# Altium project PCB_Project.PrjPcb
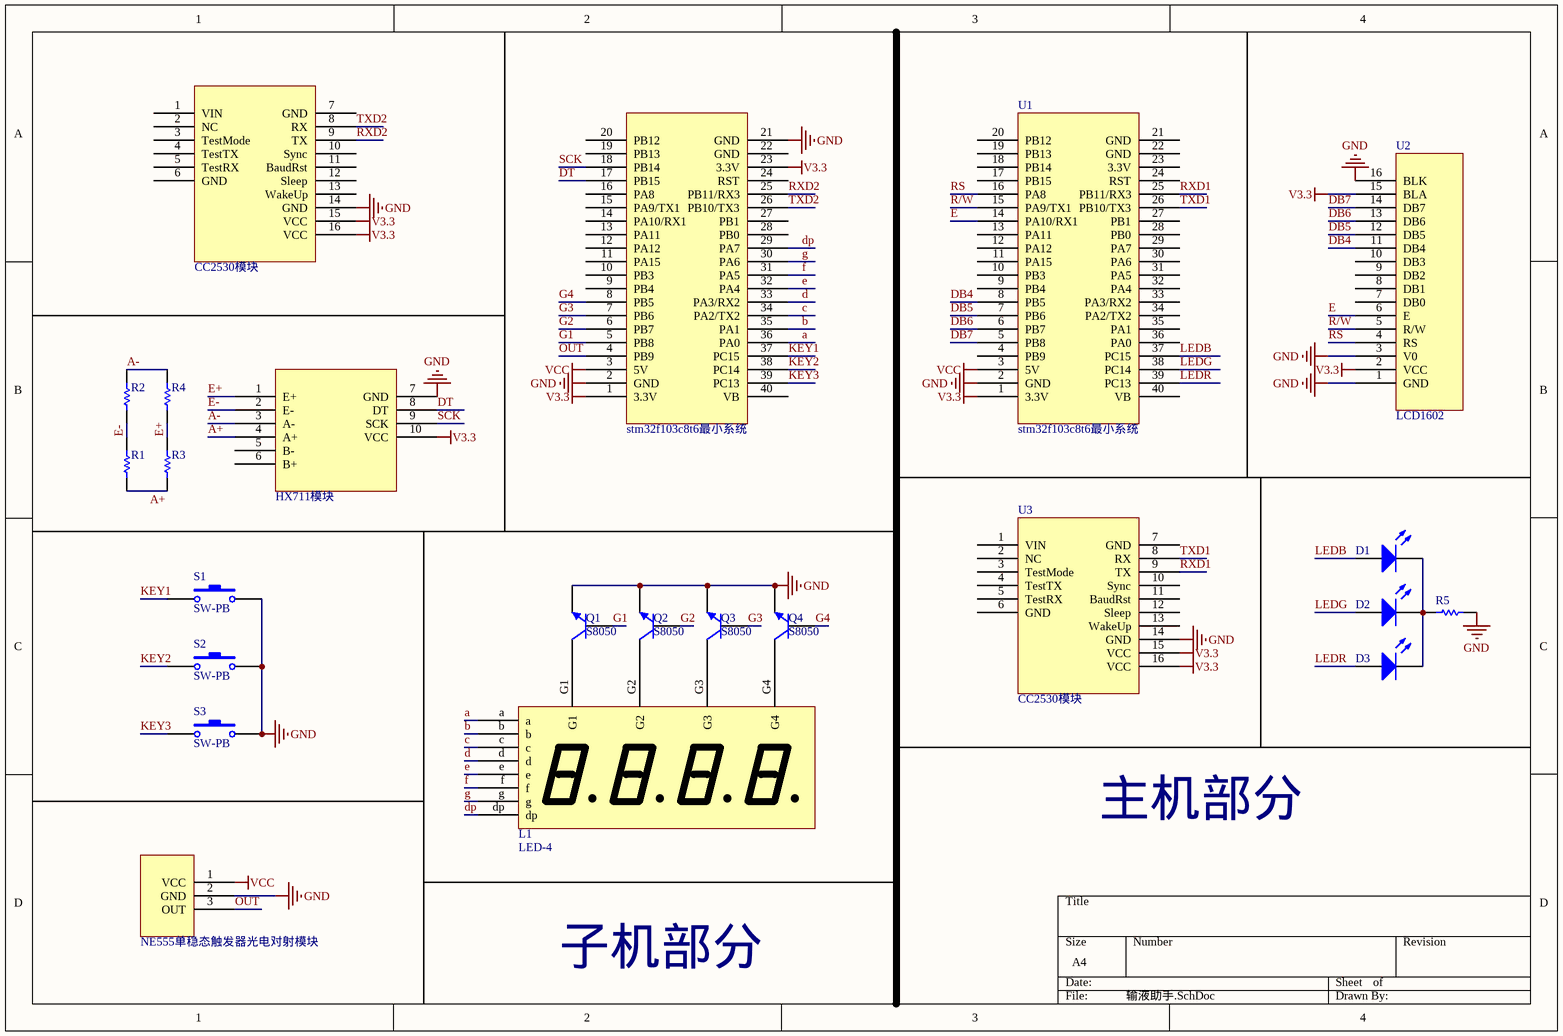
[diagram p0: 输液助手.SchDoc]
1 sheet, 23 parts. Net scope: global (net labels, ports and power ports of the same name join across sheets).

## Sheet 输液助手.SchDoc
size A4

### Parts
D1  LED0  [LED-0]  (value not drawn)
D2  LED0  [LED-0]  (value not drawn)
D3  LED0  [LED-0]  (value not drawn)
L1  LED-4
Q1  S8050  [TO-226-AA]
Q2  S8050  [TO-226-AA]
Q3  S8050  [TO-226-AA]
Q4  S8050  [TO-226-AA]
R1  Res1  [AXIAL-0.3]  (value not drawn)
R2  Res1  [AXIAL-0.3]  (value not drawn)
R3  Res1  [AXIAL-0.3]  (value not drawn)
R4  Res1  [AXIAL-0.3]  (value not drawn)
R5  Res1  [AXIAL-0.3]  (value not drawn)
S1  SW-PB  [SPST-2]
S2  SW-PB  [SPST-2]
S3  SW-PB  [SPST-2]
U1  stm32f103c8t6最小系统
U2  LCD1602
U3  CC2530模块
U4  stm32f103c8t6最小系统
U5  CC2530模块
U6  HX711模块
U7  NE555单稳态触发器光电对射模块

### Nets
GND: Q1.3(E) Q2.3(E) Q3.3(E) Q4.3(E) R5.2 S1.2 S2.2 S3.2 U1.2(GND) U2.1(GND) U2.3(V0) U2.16(BLK) U3.14(GND) U4.2(GND) U4.21(GND) U5.14(GND) U6.7(GND) U7.2(GND)
V3.3: U1.1(3.3V) U2.2(VCC) U2.15(BLA) U3.15(VCC) U3.16(VCC) U4.1(3.3V) U4.23(3.3V) U5.15(VCC) U5.16(VCC) U6.10(VCC)
VCC: U1.3(5V) U4.3(5V) U7.1(VCC)
a: L1.a U4.36(PA0)
A+: R1.1 R3.1 U6.4(A+)
A-: R2.2 R4.2 U6.3(A-)
b: L1.b U4.35(PA1)
c: L1.c U4.34(PA2/TX2)
d: L1.d U4.33(PA3/RX2)
DB4: U1.8(PB5) U2.11(DB4)
DB5: U1.7(PB6) U2.12(DB5)
DB6: U1.6(PB7) U2.13(DB6)
DB7: U1.5(PB8) U2.14(DB7)
dp: L1.dp U4.29(PA7)
DT: U4.17(PB15) U6.8(DT)
e: L1.e U1.14(PA10/RX1) U2.6(E) U4.32(PA4)
E+: R3.2 R4.1 U6.1(E+)
E-: R1.2 R2.1 U6.2(E-)
f: L1.f U4.31(PA5)
g: L1.g U4.30(PA6)
G1: Q1.2(B) U4.5(PB8)
G2: Q2.2(B) U4.6(PB7)
G3: Q3.2(B) U4.7(PB6)
G4: Q4.2(B) U4.8(PB5)
KEY1: S1.1 U4.37(PC15)
KEY2: S2.1 U4.38(PC14)
KEY3: S3.1 U4.39(PC13)
LEDB: D1.1(A) U1.37(PC15)
LEDG: D2.1(A) U1.38(PC14)
LEDR: D3.1(A) U1.39(PC13)
OUT: U4.4(PB9) U7.3(OUT)
R/W: U1.15(PA9/TX1) U2.5(R/W)
RS: U1.16(PA8) U2.4(RS)
RXD1: U1.25(PB11/RX3) U3.9(TX)
RXD2: U4.25(PB11/RX3) U5.9(TX)
SCK: U4.18(PB14) U6.9(SCK)
TXD1: U1.26(PB10/TX3) U3.8(RX)
TXD2: U4.26(PB10/TX3) U5.8(RX)
NetD1_2: D1.2(K) D2.2(K) D3.2(K) R5.1
NetL1_G1: L1.G1 Q1.1(C)
NetL1_G2: L1.G2 Q2.1(C)
NetL1_G3: L1.G3 Q3.1(C)
NetL1_G4: L1.G4 Q4.1(C)

Not connected (* = marked no-connect by the designer): U1 4(PB9) 9(PB4) 10(PB3) 11(PA15) 12(PA12) 13(PA11) 17(PB15) 18(PB14) 19(PB13) 20(PB12) 21(GND) 22(GND) 23(3.3V) 24(RST) 27(PB1) 28(PB0) 29(PA7) 30(PA6) 31(PA5) 32(PA4) 33(PA3/RX2) 34(PA2/TX2) 35(PA1) 36(PA0) 40(VB); U2 7(DB0) 8(DB1) 9(DB2) 10(DB3); U3 1(VIN) 2(NC) 3(TestMode) 4(TestTX) 5(TestRX) 6(GND) 7(GND) 10(Sync) 11(BaudRst) 12(Sleep) 13(WakeUp); U4 9(PB4) 10(PB3) 11(PA15) 12(PA12) 13(PA11) 14(PA10/RX1) 15(PA9/TX1) 16(PA8) 19(PB13) 20(PB12) 22(GND) 24(RST) 27(PB1) 28(PB0) 40(VB); U5 1(VIN) 2(NC) 3(TestMode) 4(TestTX) 5(TestRX) 6(GND) 7(GND) 10(Sync) 11(BaudRst) 12(Sleep) 13(WakeUp); U6 5(B-) 6(B+)

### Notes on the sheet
- 主机部分
- 子机部分

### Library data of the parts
D1-D3 = LED0: Typical INFRARED GaAs LED
Q1-Q4 = NPN: NPN Bipolar Transistor
R1-R5 = Res1: Resistor; Value: 1K
S1-S3 = SW-PB: Switch
U7 = LM393光电对射模块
